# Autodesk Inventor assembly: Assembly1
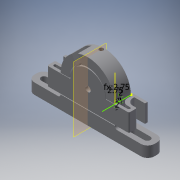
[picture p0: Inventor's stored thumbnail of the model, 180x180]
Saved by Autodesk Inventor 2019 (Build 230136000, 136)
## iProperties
Created: 2019-05
Part Number: Assembly1
Document SubType Name: Assembly
Designer: Chloe
Author: Chloe
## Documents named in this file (3)
- C:\Users\Chloe\Desktop\Assembly1.iam
- C:\Users\Chloe\Desktop\2mm Rb cell holder.ipt
- C:\Users\Chloe\Desktop\2mm Rb cell holder cover.ipt
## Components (2 placed, 2 different names)
1. 2mm Rb cell holder:1
2. 2mm Rb cell holder cover:1
